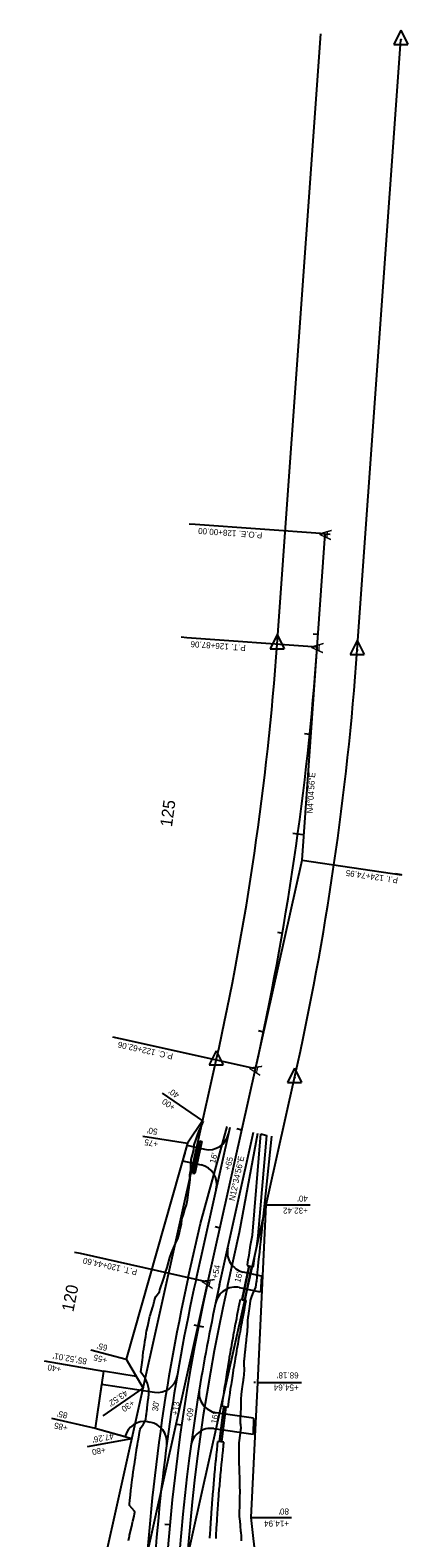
# Model space of a CAD drawing. Extents: x 609264 to 611265, y 427753 to 431566.
# Drawn here: x 610757 to 611133, y 430065 to 431566 of the extents above; entities that cross this region are included whole.
import ezdxf

# ---------------------------------------------------------------- set-up
doc = ezdxf.new("R2010")
doc.units = 0
for name, color, linetype in [('R_Drainage', 7, 'Continuous'), ('R_Drainage Stage 2', 7, 'Continuous'), ('R_Drive', 7, 'Continuous'), ('R_Drive Annot', 7, 'Continuous'), ('R_Drive Annot Stage 2', 7, 'Continuous'), ('R_Drive Stage 2', 7, 'Continuous'), ('R_Horz Alg', 7, 'Continuous'), ('R_Horz Alg Annot', 7, 'Continuous'), ('R_Horz Alg Station', 7, 'Continuous'), ('R_Horz Alg Station Annot', 7, 'Continuous'), ('R_Horz Bearings', 7, 'Continuous'), ('R_Proposed Const Limits', 7, 'Continuous'), ('R_Proposed Const Limits S2', 7, 'Continuous'), ('R_Proposed Road', 7, 'Continuous'), ('R_Proposed Road Stage 2', 7, 'Continuous'), ('R_Proposed Shoulder', 7, 'Continuous'), ('R_Proposed Shoulder Stage 2', 7, 'Continuous'), ('R_ROW', 7, 'Continuous'), ('R_ROW Annot', 7, 'Continuous'), ('R_Temp Easement', 7, 'Continuous'), ('S_EXIST_ROW', 7, 'Continuous')]:
    doc.layers.add(name, color=color, linetype=linetype)

msp = doc.modelspace()

# ---------------------------------------------------------------- linework, layer by layer
at = {"layer": 'R_Drainage'}
for p, q in [((610978.4, 430366.5), (610986.9, 430467.2)), ((610984.3, 430365.8), (610992.8, 430465.8)), ((610986.9, 430467.2), (610992.8, 430465.8)), ((610974.9, 430335.7), (610968, 430302.2)), ((610975.1, 430335.7), (610968.2, 430302.1)), ((610977.5, 430335.2), (610970.6, 430301.7)), ((610977.7, 430335.2), (610970.8, 430301.6)), ((610973.4, 430336.1), (610979.2, 430334.8)), ((610975.2, 430335.7), (610977.4, 430335.2)), ((610966.5, 430302.5), (610972.4, 430301.3)), ((610968.3, 430302.1), (610970.5, 430301.7)), ((610979.9, 430220), (610981.4, 430219.9)), ((610949.5, 430195.6), (610945.4, 430160.8)), ((610949.7, 430195.6), (610945.6, 430160.8)), ((610951.7, 430195.3), (610947.6, 430160.6)), ((610951.9, 430195.3), (610947.8, 430160.5)), ((610954.1, 430194.8), (610948.2, 430196)), ((610949.5, 430195.6), (610951.9, 430195.3)), ((610950, 430160.3), (610944.1, 430160.9)), ((610947.8, 430160.5), (610945.4, 430160.8))]:
    msp.add_line(p, q, dxfattribs=at)
for points in [[(610973.4, 430336.1), (610973.5, 430336.8), (610974.3, 430341.7), (610975.1, 430346.6), (610975.9, 430351.6), (610976.7, 430356.5), (610977.5, 430361.5), (610978.4, 430366.5)], [(610979.2, 430334.8), (610979.4, 430335.7), (610980.2, 430340.7), (610981, 430345.7), (610981.8, 430350.6), (610982.7, 430355.6), (610983.5, 430360.5), (610984.3, 430365.8)], [(610948.2, 430196), (610949, 430201.3), (610949, 430201.6), (610949.7, 430206.1), (610950.3, 430210.1), (610950.4, 430211), (610951.1, 430215.8), (610951.6, 430218.7), (610951.9, 430220.7), (610952.5, 430225), (610952.6, 430225.5), (610952.9, 430227.2), (610953.4, 430230.4), (610954.2, 430235.2), (610954.2, 430235.4), (610954.3, 430235.7), (610955, 430240), (610955.3, 430241.7), (610955.7, 430244.2), (610955.8, 430244.9), (610956.6, 430249.7), (610957, 430252), (610957.1, 430252.7), (610957.5, 430254.5), (610958.3, 430259.4), (610958.6, 430261.2), (610959.2, 430264.2), (610960, 430269), (610960.2, 430269.7), (610960.9, 430273.9), (610961.7, 430278.1), (610961.8, 430278.7), (610962.2, 430280.4), (610962.8, 430283.5), (610963.3, 430286.6), (610963.7, 430288.3), (610964.6, 430293.1), (610965, 430295.1), (610965.6, 430298), (610966.5, 430302.5)], [(610954.1, 430194.8), (610954.2, 430195.6), (610954.9, 430200.4), (610954.9, 430200.7), (610955.6, 430205.2), (610956.2, 430209.2), (610956.3, 430210.1), (610957.1, 430214.9), (610957.5, 430217.7), (610957.8, 430219.7), (610958.5, 430224), (610958.6, 430224.6), (610958.8, 430226.2), (610959.3, 430229.4), (610960.1, 430234.2), (610960.1, 430234.4), (610960.2, 430234.7), (610960.9, 430239.1), (610961.2, 430240.7), (610961.6, 430243.2), (610961.7, 430243.9), (610962.5, 430248.7), (610962.9, 430251), (610963.1, 430251.7), (610963.4, 430253.5), (610964.2, 430258.3), (610964.5, 430260.1), (610965.1, 430263.1), (610966, 430268), (610966.1, 430268.6), (610966.8, 430272.8), (610967.6, 430277), (610967.7, 430277.6), (610968.1, 430279.3), (610968.6, 430282.4), (610969.2, 430285.5), (610969.6, 430287.2), (610970.5, 430292), (610970.9, 430293.9), (610971.4, 430296.8), (610972.4, 430301.3)], [(610936.2, 430064.6), (610936.5, 430069.5), (610936.7, 430073), (610936.7, 430074.4), (610937.1, 430079.3), (610937.1, 430079.3), (610937.2, 430081.6), (610937.3, 430083.3), (610937.4, 430084.2), (610937.7, 430089.1), (610937.8, 430090.2), (610938, 430094), (610938.4, 430098.7), (610938.4, 430098.8), (610938.8, 430103.7), (610939.1, 430107.3), (610939.1, 430108.4), (610939.2, 430108.6), (610939.6, 430113.5), (610939.8, 430115.9), (610939.9, 430117.3), (610940, 430118.4), (610940.4, 430123.3), (610940.5, 430124.5), (610940.6, 430125.6), (610940.8, 430128.1), (610941.3, 430133), (610941.3, 430133.1), (610941.4, 430134.6), (610941.7, 430137.9), (610942.1, 430141.6), (610942.2, 430142.8), (610942.7, 430147.7), (610942.9, 430150.2), (610943.2, 430152.5), (610943.7, 430157.4), (610943.8, 430158.8), (610943.9, 430159.4), (610944.1, 430160.9)], [(610942.2, 430064.3), (610942.5, 430069.2), (610942.7, 430072.6), (610942.7, 430074.1), (610943, 430078.9), (610943, 430078.9), (610943.2, 430081.2), (610943.3, 430082.9), (610943.4, 430083.8), (610943.7, 430088.7), (610943.8, 430089.7), (610944, 430093.5), (610944.4, 430098.3), (610944.4, 430098.4), (610944.8, 430103.3), (610945, 430106.8), (610945.1, 430108), (610945.1, 430108.1), (610945.5, 430113), (610945.7, 430115.4), (610945.9, 430116.8), (610945.9, 430117.9), (610946.4, 430122.7), (610946.5, 430124), (610946.6, 430125.1), (610946.8, 430127.6), (610947.2, 430132.5), (610947.2, 430132.5), (610947.4, 430134), (610947.7, 430137.3), (610948.1, 430141.1), (610948.2, 430142.2), (610948.7, 430147.1), (610948.9, 430149.6), (610949.2, 430151.9), (610949.7, 430156.8), (610949.8, 430158.1), (610949.9, 430158.8), (610950, 430160.3)]]:
    msp.add_lwpolyline(points, dxfattribs=at)
at = {"layer": 'R_Drainage Stage 2'}
for p, q in [((610926, 430460.3), (610918.8, 430428.3)), ((610926.2, 430460.2), (610919, 430428.2)), ((610928, 430459.8), (610920.8, 430427.8)), ((610928.2, 430459.8), (610921, 430427.8)), ((610926, 430460.3), (610928.2, 430459.8)), ((610918.8, 430428.3), (610921, 430427.8))]:
    msp.add_line(p, q, dxfattribs=at)
at = {"layer": 'R_Drive'}
for p, q in [((610987.6, 430325.6), (610969.1, 430329.7)), ((610987.6, 430325.6), (610986.5, 430309.5)), ((610986.5, 430309.5), (610965.7, 430314.1)), ((610979.7, 430184), (610942.3, 430189.6)), ((610979.7, 430184), (610979.3, 430167.9)), ((610979.3, 430167.9), (610940, 430173.7))]:
    msp.add_line(p, q, dxfattribs=at)
for centre, start, end in [((610973.5, 430349.2), 167.4178, 257.4178), ((610961.4, 430294.6), 77.4178, 167.9853), ((610945.3, 430209.4), 170.6314, 261.4858), ((610937, 430154), 81.4858, 172.3401)]:
    msp.add_arc(centre, 20, start, end, dxfattribs=at)
at = {"layer": 'R_Drive Stage 2'}
for p, q in [((610913.2, 430455.9), (610930.8, 430452)), ((610908.8, 430440.5), (610927.4, 430436.4)), ((610828.3, 430217.9), (610880.8, 430210)), ((610874, 430180.7), (610876.3, 430180.3))]:
    msp.add_line(p, q, dxfattribs=at)
for points in [[(610913.2, 430455.9), (610911, 430448.2), (610908.8, 430440.5)], [(610828.3, 430217.9), (610821.7, 430174.2), (610851.6, 430165.9)]]:
    msp.add_lwpolyline(points, dxfattribs=at)
for centre, start, end in [((610935.2, 430471.5), 257.4178, 347.4178), ((610923, 430416.9), 347.4178, 77.4178), ((610883.8, 430229.7), 261.3658, 350.333), ((610871, 430160.9), 81.3658, 165.5515), ((610873.3, 430160.5), 352.3985, 81.3658)]:
    msp.add_arc(centre, 20, start, end, dxfattribs=at)
at = {"layer": 'R_Horz Alg'}
for p, q in [((611043, 430952.1), (611051, 431064.7)), ((610934.1, 430319.7), (610981.5, 430531.9))]:
    msp.add_line(p, q, dxfattribs=at)
for centre, radius, start, end in [((608185.5, 431156), 2864.8, 347.4178, 355.9178), ((612798.1, 429903.7), 1909.9, 167.4178, 188.51)]:
    msp.add_arc(centre, radius, start, end, dxfattribs=at)
at = {"layer": 'R_Horz Alg Annot'}
msp.add_line((610856.6, 429972.7), (610934.1, 430319.7), dxfattribs=at)
msp.add_lwpolyline([(610981.5, 430531.9), (611027.9, 430739.7), (611043, 430952.1)], dxfattribs=at)
at = {"layer": 'R_Horz Alg Station'}
for points in [[(611051, 431064.7), (610921.4, 431074), (610915.4, 431074.4)], [(611046.1, 431065.1), (611056, 431064.4)], [(611043, 430952.1), (610913.3, 430961.3), (610907.4, 430961.8)], [(611038.9, 430965.3), (611043.9, 430965)], [(611030.5, 430865.9), (611035.5, 430865.3)], [(611018.7, 430766.7), (611028.6, 430765.4)], [(611027.9, 430739.7), (611126.8, 430725.2), (611120.9, 430726.1)], [(611003.3, 430668.1), (611008.3, 430667.2)], [(610984.6, 430570.1), (610989.5, 430569)], [(610981.5, 430531.9), (610854.6, 430560.3), (610839.5, 430563.6)], [(610963.1, 430472.5), (610968, 430471.4)], [(610941.3, 430374.9), (610946.2, 430373.8)], [(610934.1, 430319.7), (610807.2, 430348), (610801.4, 430349.3)], [(610920, 430277), (610929.8, 430275.1)], [(610903, 430178.2), (610908, 430177.5)], [(610891.3, 430078.7), (610896.2, 430078.2)]]:
    msp.add_lwpolyline(points, dxfattribs=at)
at = {"layer": 'R_Proposed Const Limits'}
msp.add_lwpolyline([(610997.4, 430465.1), (610986.5, 430359.6), (610986, 430354.6), (610985.4, 430349.6), (610984.8, 430344.7), (610984.3, 430339.7), (610983.7, 430334.7), (610983.3, 430329.6), (610982.9, 430324.6), (610982.4, 430320.5), (610982.2, 430319.6), (610981.4, 430314.7), (610979.5, 430310), (610979.3, 430309.6), (610977.7, 430305.4), (610976.3, 430301.5), (610976.2, 430300.7), (610975.6, 430295.8), (610975.3, 430292.9), (610974.9, 430291), (610974.2, 430286.2), (610973.9, 430284.5), (610973.5, 430281.3), (610973.5, 430278.1), (610973.5, 430276.4), (610973.5, 430275.8), (610973.4, 430271.4), (610972.8, 430267.2), (610972.7, 430266.6), (610972.1, 430261.7), (610971.8, 430258.7), (610971.7, 430256.8), (610971.2, 430252), (610971, 430250.1), (610970.9, 430249.4), (610970.6, 430247.1), (610970.1, 430242.3), (610970, 430241.6), (610970, 430239), (610970, 430237.3), (610970.2, 430232.9), (610970.2, 430232.5), (610970.2, 430232.4), (610969.9, 430227.5), (610969.6, 430224.3), (610969.4, 430222.6), (610969.3, 430222.1), (610968.7, 430217.8), (610968.4, 430215.8), (610968, 430213), (610967.4, 430208.2), (610967.4, 430207.3), (610967, 430203.3), (610966.9, 430198.8), (610966.9, 430198.4), (610966.8, 430193.5), (610966.6, 430190.2), (610966.6, 430188.6), (610966.3, 430183.8), (610966.3, 430182.8), (610966.3, 430181.6), (610966.4, 430178.9), (610966.5, 430177.9), (610966.8, 430173.9), (610966.7, 430172.9), (610966.3, 430169.1), (610966.3, 430169.1), (610965.6, 430164.5), (610965.6, 430164.3), (610965, 430159.5), (610965, 430157.7), (610965, 430156.6), (610965, 430156), (610965, 430154.6), (610965, 430154.1), (610964.9, 430149.7), (610964.8, 430147.4), (610964.9, 430144.8), (610965, 430139.9), (610965, 430138.8), (610965.2, 430135), (610965.4, 430131.7), (610965.4, 430130.2), (610965.4, 430130.1), (610965.5, 430125.3), (610965.6, 430122.7), (610965.6, 430121.6), (610965.7, 430120.4), (610965.6, 430115.5), (610965.7, 430114.4), (610965.8, 430113), (610966, 430110.6), (610965.6, 430105.8), (610965.6, 430105.6), (610965.6, 430104.5), (610965.7, 430100.9), (610965.6, 430096.1), (610965.6, 430096), (610965.3, 430091.3), (610965.3, 430087.5), (610965.4, 430086.4), (610965.8, 430081.5), (610965.9, 430080.6), (610966.1, 430078.9), (610966.2, 430076.7), (610966.2, 430076.6), (610966.6, 430071.8), (610966.8, 430070.3), (610967.1, 430066.9), (610967.4, 430062)], dxfattribs=at)
at = {"layer": 'R_Proposed Const Limits S2'}
msp.add_lwpolyline([(610855, 430062.5), (610855.9, 430066.6), (610856.2, 430067.7), (610857, 430071.3), (610857, 430071.6), (610858.2, 430076.6), (610858.9, 430080.1), (610859.2, 430081.6), (610860.6, 430086.6), (610860.6, 430086.6), (610860.9, 430089), (610861.2, 430090.7), (610861.1, 430091.7), (610856.1, 430097.3), (610856.2, 430098.4), (610856.5, 430102.4), (610857, 430107.4), (610857, 430107.5), (610857.5, 430112.6), (610857.9, 430116.3), (610858.1, 430117.5), (610858.1, 430117.6), (610858.7, 430122.7), (610859.1, 430125.2), (610859.2, 430126.6), (610859.4, 430127.8), (610860.1, 430132.8), (610860.3, 430134.1), (610860.5, 430135.3), (610860.9, 430137.9), (610861.6, 430142.9), (610861.6, 430143), (610861.9, 430144.6), (610862.4, 430148), (610862.9, 430151.9), (610863.1, 430153.1), (610864, 430158.1), (610864.5, 430160.7), (610864.9, 430163.1), (610865.6, 430167.6), (610865.7, 430168.2), (610866, 430169.6), (610866.1, 430170.3), (610866.3, 430171.4), (610866.7, 430173.2), (610867, 430174.2), (610869.6, 430177.9), (610869.9, 430178.1), (610872.3, 430182.7), (610872.8, 430186.7), (610872.9, 430187.8), (610873.4, 430191.8), (610873.5, 430192.8), (610873.8, 430195.6), (610874, 430196.8), (610874.1, 430197.9), (610874.7, 430202.9), (610874.9, 430204.5), (610875.3, 430208), (610875.4, 430213.1), (610875.3, 430213.5), (610873.9, 430218.6), (610872, 430223.2), (610871.6, 430224.1), (610867.3, 430230), (610867.7, 430233), (610867.9, 430235.1), (610868.6, 430239.6), (610868.8, 430240.2), (610869.1, 430241.9), (610869.2, 430245.3), (610869.8, 430250.4), (610869.9, 430250.9), (610870.6, 430255.5), (610870.9, 430257.2), (610871.3, 430259.8), (610871.4, 430260.6), (610872.2, 430265.6), (610872.6, 430268), (610872.8, 430268.7), (610873.1, 430270.7), (610874.2, 430275.7), (610874.5, 430277.5), (610874.5, 430277.6), (610875.2, 430280.7), (610876.4, 430285.7), (610876.6, 430286.4), (610878, 430290.6), (610879.3, 430295), (610879.5, 430295.6), (610880.7, 430300.5), (610881.5, 430303.8), (610882.4, 430305.4), (610885.8, 430309.9), (610886.4, 430311.9), (610887.4, 430314.8), (610889, 430319.7), (610889.3, 430320.5), (610889.3, 430320.6), (610890.5, 430324.6), (610891.9, 430329.1), (610892, 430329.5), (610893.5, 430334.3), (610894.9, 430339.1), (610896.1, 430344), (610898, 430348.7), (610900, 430353.3), (610902, 430358), (610904.3, 430362.6), (610904.3, 430362.6), (610905.4, 430367.5), (610906.6, 430372.4), (610907.7, 430377.2), (610908.1, 430382.3), (610909.7, 430387), (610911.3, 430391.8), (610912.7, 430396.6), (610913.9, 430401.5), (610914.4, 430406.5), (610914.7, 430409.5), (610915, 430411.5), (610915.7, 430416.4), (610916.3, 430421.4), (610916, 430426.6), (610917.2, 430431.5), (610917.1, 430436.6), (610917.4, 430441.7), (610918.9, 430446.5), (610920, 430451.4), (610920.5, 430456.4), (610920.7, 430457.3), (610922, 430461.1), (610923.7, 430465.9), (610925.3, 430470.6), (610927.6, 430475.3), (610929.9, 430479.9)], dxfattribs=at)
at = {"layer": 'R_Proposed Road'}
msp.add_line((610945.8, 430317.1), (610979.7, 430468.8), dxfattribs=at)
for start, end in [(167.4178, 170.4537), (170.4537, 188.51)]:
    msp.add_arc((612798.1, 429903.7), 1897.9, start, end, dxfattribs=at)
at = {"layer": 'R_Proposed Road Stage 2'}
msp.add_line((610922.4, 430322.3), (610956.2, 430474), dxfattribs=at)
msp.add_arc((612798.1, 429903.7), 1921.9, 167.4178, 176.5959, dxfattribs=at)
at = {"layer": 'R_Proposed Shoulder'}
for p, q in [((610965.7, 430369.4), (610984, 430468)), ((610953.6, 430315.4), (610965.7, 430369.4))]:
    msp.add_line(p, q, dxfattribs=at)
msp.add_arc((612798.1, 429903.7), 1889.9, 167.4178, 188.51, dxfattribs=at)
at = {"layer": 'R_Proposed Shoulder Stage 2'}
for p, q in [((610926.7, 430378.1), (610953.4, 430474.7)), ((610914.6, 430324.1), (610926.7, 430378.1))]:
    msp.add_line(p, q, dxfattribs=at)
msp.add_arc((612798.1, 429903.7), 1929.9, 167.4178, 177.9781, dxfattribs=at)
at = {"layer": 'R_ROW'}
for points in [[(610928.9, 430480.1), (610913.7, 430457.9), (610852.6, 430243), (610869.5, 430214.1)], [(611015.6, 429741.9), (610995.6, 429920.5), (610990.9, 429963.1), (610986.4, 430003.2), (610982.6, 430037.8), (610977.3, 430085.2), (610983.7, 430219.8), (610992.3, 430396.7), (610992.3, 430396.7)]]:
    msp.add_lwpolyline(points, dxfattribs=at)
at = {"layer": 'R_ROW Annot'}
for p, q in [((610888.7, 430507.9), (610928.9, 430480.1)), ((610869.3, 430465.1), (610913.7, 430457.9)), ((610992.3, 430396.7), (611035.9, 430396.7)), ((610771, 430241.2), (610830.3, 430231)), ((610817.4, 430252.2), (610852.6, 430243)), ((610829.7, 430186.5), (610869.5, 430214.1)), ((610983.7, 430219.8), (611027.4, 430219.8)), ((610778.2, 430184.1), (610821.7, 430174.2)), ((610814.1, 430155.8), (610858.4, 430164)), ((610977.3, 430085.2), (611017.4, 430085.2))]:
    msp.add_line(p, q, dxfattribs=at)
at = {"layer": 'R_Temp Easement'}
msp.add_line((610862.8, 430225.6), (610830.3, 430231), dxfattribs=at)
msp.add_lwpolyline([(610830.3, 430231), (610821.7, 430174.2), (610858.4, 430164)], dxfattribs=at)
at = {"layer": 'S_EXIST_ROW'}
for p, q in [((611003.1, 430954.9), (611046.5, 431562.6)), ((611126.3, 431566.4), (611119.2, 431552.2)), ((611126.3, 431566.4), (611133.3, 431552.2)), ((611082.9, 430949.2), (611126.3, 431556.9)), ((611119.2, 431552.2), (611133.3, 431552.2)), ((611126.3, 431556.9), (611126.3, 431556.9)), ((611003.1, 430964.4), (610996.1, 430950.2)), ((611003.1, 430964.4), (611010.1, 430950.2)), ((610996.1, 430950.2), (611010.1, 430950.2)), ((611003.1, 430954.9), (611003.1, 430954.9)), ((611082.9, 430958.7), (611075.9, 430944.5)), ((611082.9, 430958.7), (611089.9, 430944.5)), ((611082.9, 430949.2), (611082.9, 430949.2)), ((611075.9, 430944.5), (611089.9, 430944.5)), ((610757.1, 429710.3), (610942.4, 430540.7)), ((610942.5, 430550.1), (610935.4, 430535.9)), ((610942.4, 430540.7), (610942.4, 430540.7)), ((610942.5, 430550.1), (610949.4, 430535.9)), ((610935.4, 430535.9), (610949.4, 430535.9)), ((611020.5, 430532.7), (611013.5, 430518.5)), ((611020.5, 430532.7), (611027.5, 430518.5)), ((610822.6, 429636.5), (611020.5, 430523.2)), ((611013.5, 430518.5), (611027.5, 430518.5)), ((611020.5, 430523.2), (611020.5, 430523.2))]:
    msp.add_line(p, q, dxfattribs=at)
for centre, radius in [((611126.3, 431556.9), 0.24), ((611126.3, 431556.9), 0.12), ((611003.1, 430954.9), 0.24), ((611003.1, 430954.9), 0.12), ((611082.9, 430949.2), 0.24), ((611082.9, 430949.2), 0.12), ((610942.4, 430540.7), 0.24), ((610942.4, 430540.7), 0.12), ((611020.5, 430523.2), 0.24), ((611020.5, 430523.2), 0.12)]:
    msp.add_circle(centre, radius, dxfattribs=at)
for radius in [2824.8, 2904.8]:
    msp.add_arc((608185.5, 431156), radius, 347.4178, 355.9178, dxfattribs=at)

# ---------------------------------------------------------------- texts
at = {"layer": 'R_Drive Annot'}
for s, rotation, p in [('+54', 77.2997, (610943.7, 430322.7)), ("16'", 75.4403, (610966.2, 430318.7)), ('+09', 82.371, (610918.1, 430180.4)), ("16'", 79.6001, (610942.9, 430178.3))]:
    msp.add_text(s, height=6, rotation=rotation, dxfattribs=at).set_placement(p)
at = {"layer": 'R_Drive Annot Stage 2'}
for s, rotation, p in [("16'", 75.4403, (610941.3, 430437.4)), ('+65', 74.8127, (610955.9, 430430.3)), ("30'", 81.9384, (610884.3, 430190.6)), ('+13', 82.371, (610904.2, 430186.7))]:
    msp.add_text(s, height=6, rotation=rotation, dxfattribs=at).set_placement(p)
at = {"layer": 'R_Horz Alg'}
for rotation, p in [(85.9178, (611056.6, 431058.3)), (85.9178, (611048.6, 430945.7)), (77.4178, (610986, 430524.8)), (77.4178, (610986, 430524.8)), (77.4178, (610938.7, 430312.5)), (77.4178, (610938.7, 430312.5)), (77.4178, (610938.7, 430312.5))]:
    msp.add_text('A', height=12, rotation=rotation, dxfattribs=at).set_placement(p)
at = {"layer": 'R_Horz Alg Station Annot'}
for s, height, rotation, p in [('P.O.E. 128+00.00', 6, 175.9178, (610988.5, 431066.2)), ('P.T. 126+87.06', 6, 175.9178, (610972, 430954.1)), ('125', 12, 82.1766, (610898.3, 430772.4)), ('P.I. 124+74.95', 6, 171.6678, (611123.8, 430722.6)), ('P.C. 122+62.06', 6, 167.4178, (610899.8, 430547.1)), ('P.T. 120+44.60', 6, 167.4178, (610864.2, 430332.2)), ('120', 12, 78.7558, (610800.1, 430289.4))]:
    msp.add_text(s, height=height, rotation=rotation, dxfattribs=at).set_placement(p)
at = {"layer": 'R_Horz Bearings'}
for s, rotation, p in [('N4%%d04\'56"E', 86.2399, (611038.5, 430786.1)), ('N12%%d34\'56"E', 77.6114, (610960.7, 430400.1))]:
    msp.add_text(s, height=6, rotation=rotation, dxfattribs=at).set_placement(p)
at = {"layer": 'R_ROW Annot'}
for s, rotation, p in [("40'", 145.3831, (610906.3, 430507.1)), ('+00 ', 145.3831, (610902.3, 430495.2)), ("50'", 170.7914, (610884.3, 430472.2)), ('+75', 170.7914, (610884.8, 430459.9)), ("40'", 180, (611033.7, 430405.8)), ('+32.42', 180, (611033.7, 430393.8)), ("65'", 165.4128, (610834.7, 430256.7)), ("85',52.01'", 170.2497, (610814, 430243.4)), ('+55', 165.4128, (610834.3, 430244.4)), ('+40', 170.2497, (610788.4, 430235.6)), ("68.18'", 180, (611024.5, 430229.7)), ("43.52'", 214.7253, (610851.7, 430212.4)), ('+54.64', 180, (611024.5, 430217.7)), ('+30', 214.7253, (610858.5, 430202.6)), ('+85', 167.1867, (610795, 430177)), ("85'", 167.1867, (610794.8, 430189.4)), ("47.26'", 190.52, (610839.8, 430169.3)), ('+80', 190.52, (610831.7, 430155.6)), ("80'", 180, (611014.9, 430094.2)), ('+14.94', 180, (611014.9, 430082.2))]:
    msp.add_text(s, height=6, rotation=rotation, dxfattribs=at).set_placement(p)

doc.saveas('drawing.dxf')
